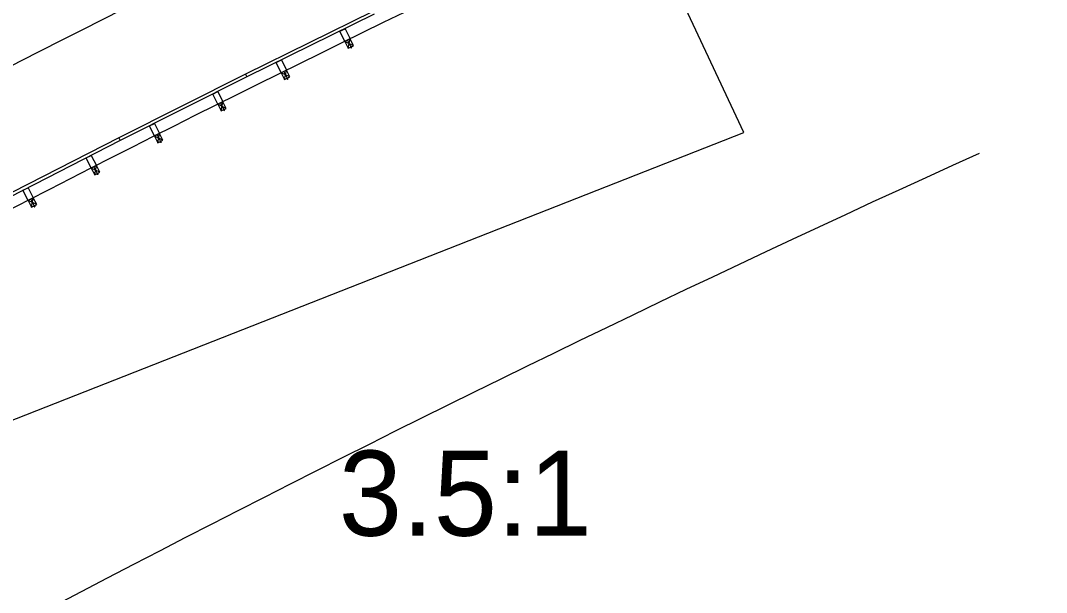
# Model space of a CAD drawing. Extents: x 24523748 to 24530451, y 6406056 to 6407486.
# Drawn here: x 24527251.4 to 24527341.8, y 6407203 to 6407253.5 of the extents above; entities that cross this region are included whole.
import ezdxf

# ---------------------------------------------------------------- set-up
doc = ezdxf.new("R2010")
doc.units = 0
for name, color, linetype in [('Cell', 7, 'Continuous'), ('dsnNonPlotable', 7, 'Continuous'), ('EdgePaved', 7, 'Continuous'), ('EdgeShoulder', 7, 'Continuous')]:
    doc.layers.add(name, color=color, linetype=linetype)

msp = doc.modelspace()

# ---------------------------------------------------------------- linework, layer by layer
at = {"layer": 'Cell'}
for p, q in [((24527282.49, 6407254.253), (24527271.272, 6407248.738)), ((24527282.609, 6407254.01), (24527271.392, 6407248.495)), ((24527279.58, 6407252.521), (24527280.029, 6407252.741)), ((24527280.022, 6407251.622), (24527279.58, 6407252.521)), ((24527280.029, 6407252.741), (24527280.471, 6407251.843)), ((24527280.471, 6407251.843), (24527280.022, 6407251.622)), ((24527280.765, 6407251.245), (24527280.022, 6407251.623)), ((24527280.246, 6407251.733), (24527280.54, 6407251.135)), ((24527280.316, 6407251.024), (24527280.471, 6407251.843)), ((24527280.583, 6407251.047), (24527280.586, 6407251.041)), ((24527273.971, 6407249.763), (24527274.42, 6407249.984)), ((24527274.413, 6407248.865), (24527273.971, 6407249.763)), ((24527274.42, 6407249.984), (24527274.862, 6407249.086)), ((24527274.862, 6407249.086), (24527274.413, 6407248.865)), ((24527275.156, 6407248.487), (24527274.413, 6407248.865)), ((24527274.638, 6407248.975), (24527274.932, 6407248.377)), ((24527274.707, 6407248.267), (24527274.862, 6407249.086)), ((24527271.271, 6407248.737), (24527260.101, 6407243.127)), ((24527271.393, 6407248.495), (24527260.222, 6407242.885)), ((24527271.271, 6407248.737), (24527271.393, 6407248.495)), ((24527271.272, 6407248.738), (24527271.392, 6407248.495)), ((24527274.975, 6407248.29), (24527274.978, 6407248.284)), ((24527268.376, 6407246.98), (24527268.823, 6407247.205)), ((24527268.825, 6407246.086), (24527268.376, 6407246.98)), ((24527268.823, 6407247.205), (24527269.273, 6407246.31)), ((24527269.273, 6407246.31), (24527268.825, 6407246.086)), ((24527269.572, 6407245.715), (24527268.826, 6407246.086)), ((24527269.049, 6407246.198), (24527269.348, 6407245.602)), ((24527269.125, 6407245.49), (24527269.273, 6407246.31)), ((24527269.392, 6407245.516), (24527269.395, 6407245.509)), ((24527262.791, 6407244.175), (24527263.238, 6407244.4)), ((24527263.238, 6407244.4), (24527263.687, 6407243.506)), ((24527263.24, 6407243.281), (24527262.791, 6407244.175)), ((24527263.687, 6407243.506), (24527263.24, 6407243.281)), ((24527263.464, 6407243.393), (24527263.763, 6407242.798)), ((24527263.54, 6407242.685), (24527263.687, 6407243.506)), ((24527260.1, 6407243.127), (24527248.972, 6407237.432)), ((24527260.223, 6407242.886), (24527249.096, 6407237.191)), ((24527260.1, 6407243.127), (24527260.223, 6407242.886)), ((24527260.101, 6407243.127), (24527260.222, 6407242.885)), ((24527263.986, 6407242.91), (24527263.24, 6407243.281)), ((24527263.807, 6407242.711), (24527263.81, 6407242.705)), ((24527257.218, 6407241.348), (24527257.664, 6407241.576)), ((24527257.664, 6407241.576), (24527258.12, 6407240.685)), ((24527257.674, 6407240.457), (24527257.218, 6407241.348)), ((24527258.12, 6407240.685), (24527257.674, 6407240.457)), ((24527257.978, 6407239.864), (24527258.12, 6407240.685)), ((24527258.423, 6407240.092), (24527257.675, 6407240.457)), ((24527257.897, 6407240.571), (24527258.201, 6407239.978)), ((24527258.245, 6407239.891), (24527258.248, 6407239.885)), ((24527251.655, 6407238.5), (24527252.1, 6407238.728)), ((24527252.111, 6407237.609), (24527251.655, 6407238.5)), ((24527252.1, 6407238.728), (24527252.556, 6407237.837)), ((24527252.556, 6407237.837), (24527252.111, 6407237.609)), ((24527252.86, 6407237.244), (24527252.111, 6407237.61)), ((24527252.334, 6407237.724), (24527252.637, 6407237.13)), ((24527252.415, 6407237.016), (24527252.556, 6407237.837)), ((24527252.682, 6407237.044), (24527252.685, 6407237.037))]:
    msp.add_line(p, q, dxfattribs=at)
for points in [[(24527280.471, 6407251.843), (24527280.022, 6407251.623), (24527280.316, 6407251.024), (24527280.765, 6407251.245)], [(24527274.862, 6407249.086), (24527274.413, 6407248.865), (24527274.707, 6407248.267), (24527275.156, 6407248.487)], [(24527269.273, 6407246.31), (24527268.826, 6407246.086), (24527269.125, 6407245.49), (24527269.572, 6407245.715)], [(24527263.687, 6407243.506), (24527263.24, 6407243.281), (24527263.54, 6407242.685), (24527263.986, 6407242.91)], [(24527258.12, 6407240.685), (24527257.675, 6407240.457), (24527257.978, 6407239.864), (24527258.423, 6407240.092)], [(24527252.556, 6407237.837), (24527252.111, 6407237.61), (24527252.415, 6407237.016), (24527252.86, 6407237.244)]]:
    msp.add_lwpolyline(points, close=True, dxfattribs=at)
for points in [[(24527280.57, 6407251.149), (24527280.589, 6407251.111), (24527280.53, 6407251.081), (24527280.511, 6407251.12)], [(24527280.577, 6407251.105), (24527280.601, 6407251.056), (24527280.566, 6407251.039), (24527280.542, 6407251.087)], [(24527274.962, 6407248.392), (24527274.981, 6407248.353), (24527274.921, 6407248.324), (24527274.902, 6407248.362)], [(24527274.968, 6407248.347), (24527274.992, 6407248.298), (24527274.957, 6407248.281), (24527274.933, 6407248.33)], [(24527269.378, 6407245.617), (24527269.397, 6407245.579), (24527269.338, 6407245.549), (24527269.319, 6407245.588)], [(24527269.385, 6407245.573), (24527269.409, 6407245.524), (24527269.375, 6407245.507), (24527269.35, 6407245.555)], [(24527263.793, 6407242.813), (24527263.812, 6407242.774), (24527263.753, 6407242.744), (24527263.733, 6407242.783)], [(24527263.8, 6407242.768), (24527263.824, 6407242.72), (24527263.789, 6407242.702), (24527263.765, 6407242.75)], [(24527258.231, 6407239.993), (24527258.25, 6407239.955), (24527258.191, 6407239.924), (24527258.171, 6407239.963)], [(24527258.238, 6407239.948), (24527258.263, 6407239.9), (24527258.228, 6407239.882), (24527258.203, 6407239.931)], [(24527252.667, 6407237.145), (24527252.687, 6407237.107), (24527252.627, 6407237.077), (24527252.608, 6407237.115)], [(24527252.674, 6407237.101), (24527252.699, 6407237.052), (24527252.664, 6407237.035), (24527252.64, 6407237.083)]]:
    msp.add_lwpolyline(points, dxfattribs=at)
at = {"layer": 'dsnNonPlotable'}
msp.add_line((24527315.182, 6407243.584), (24527295.834, 6407284.943), dxfattribs=at)
msp.add_lwpolyline([(24527166.541, 6407203.214), (24527074.481, 6407148.911), (24527315.182, 6407243.584)], dxfattribs=at)
for radius, start, end in [(1608, 97.112473, 120.076374), (1605.625, 97.112473, 120.076374), (1617.624, 115.890282, 120.534796), (1593.624, 115.890282, 120.534796), (1549.624, 114.405331, 120.534796)]:
    msp.add_arc((24527976.2, 6405830.592), radius, start, end, dxfattribs=at)
at = {"layer": 'EdgePaved'}
msp.add_arc((24527976.2, 6405830.592), 1642.624, 62.735671, 120.534796, dxfattribs=at)
at = {"layer": 'EdgeShoulder'}
for radius, start, end in [(1623.624, 112.92311, 120.534796), (1617.624, 113.013012, 120.534796), (1593.624, 115.890282, 120.534796), (1582.406, 115.890282, 120.653283)]:
    msp.add_arc((24527976.2, 6405830.592), radius, start, end, dxfattribs=at)

# ---------------------------------------------------------------- texts
at = {"layer": 'dsnNonPlotable'}
msp.add_text('3.5:1', height=7.5, dxfattribs=at).set_placement((24527279.481, 6407208.046))

doc.saveas('drawing.dxf')
